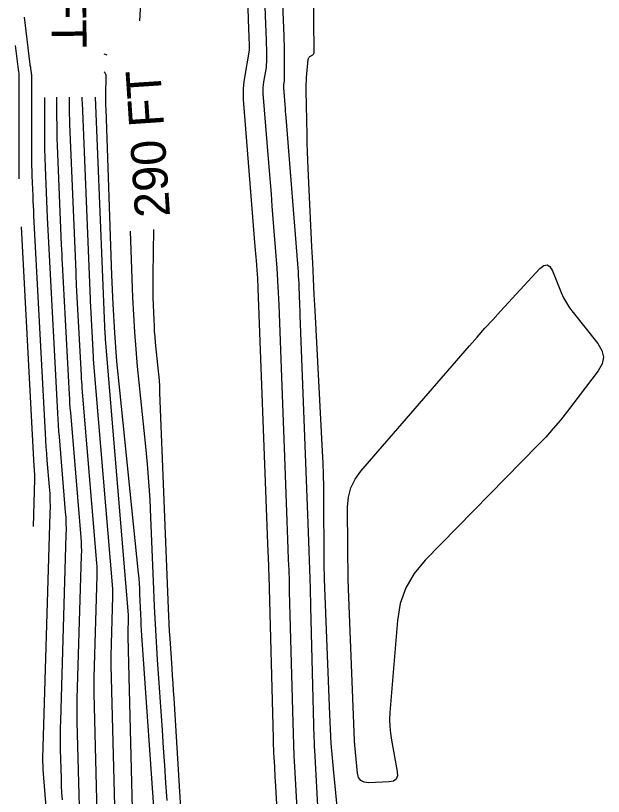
# Model space of a CAD drawing. Extents: x 1768942 to 1774819, y 723037 to 732099.
# Drawn here: x 1770904.7 to 1771006, y 723261.7 to 723396.1 of the extents above; entities that cross this region are included whole.
import ezdxf

# ---------------------------------------------------------------- set-up
doc = ezdxf.new("R2010")
doc.units = 0
doc.layers.add('R_Contour Annot', color=7, linetype='Continuous')
doc.layers.add('R_Contours', color=7, linetype='Continuous')

msp = doc.modelspace()

# ---------------------------------------------------------------- linework, layer by layer
at = {"layer": 'R_Contours'}
for points in [[(1770942.43, 723439.74), (1770944.77, 723395.9), (1770944.79, 723395.4), (1770944.82, 723394.9), (1770944.84, 723394.39), (1770944.86, 723393.89), (1770944.98, 723391.02), (1770944.98, 723390.95), (1770944.99, 723390.87), (1770944.99, 723390.8), (1770944.99, 723390.72), (1770944.99, 723390.43), (1770944.99, 723390.35), (1770944.98, 723390.28), (1770944.98, 723390.2), (1770944.97, 723390.13), (1770944.11, 723385.12), (1770943.99, 723384.26), (1770943.93, 723383.39), (1770943.92, 723382.53), (1770943.96, 723381.66), (1770945.97, 723356.33), (1770946.02, 723355.73), (1770946.07, 723355.13), (1770946.11, 723354.54), (1770946.16, 723353.94), (1770946.35, 723351.54), (1770946.39, 723350.95), (1770946.43, 723350.35), (1770946.46, 723349.75), (1770946.49, 723349.15), (1770948.03, 723308.3), (1770948.09, 723306.75), (1770948.15, 723305.2), (1770948.29, 723301.43), (1770948.31, 723300.99), (1770948.32, 723300.54), (1770948.34, 723300.09), (1770948.35, 723299.65), (1770949.08, 723271.71), (1770949.1, 723271.1), (1770949.13, 723270.49), (1770949.15, 723269.88), (1770949.18, 723269.26), (1770949.31, 723266.81), (1770949.35, 723266.2), (1770949.38, 723265.59), (1770949.42, 723264.97), (1770949.45, 723264.36), (1770951.02, 723237.64)], [(1770949.41, 723429.56), (1770950.93, 723392.61), (1770950.96, 723391.85), (1770950.98, 723391.09), (1770950.99, 723390.34), (1770951, 723389.58), (1770951.02, 723385.31), (1770951.02, 723385.18), (1770951.01, 723385.04), (1770951, 723384.91), (1770950.98, 723384.78), (1770950.89, 723384.25), (1770950.87, 723384.11), (1770950.86, 723383.98), (1770950.86, 723383.85), (1770950.87, 723383.71), (1770951.1, 723380.71), (1770951.15, 723380.17), (1770951.19, 723379.62), (1770951.23, 723379.08), (1770951.28, 723378.53), (1770953.39, 723351.91), (1770953.43, 723351.29), (1770953.47, 723350.68), (1770953.5, 723350.06), (1770953.53, 723349.44), (1770953.65, 723346.35), (1770953.69, 723345.12), (1770953.72, 723344.5), (1770955.13, 723307.22), (1770955.24, 723303.99), (1770955.35, 723300.76), (1770955.45, 723297.54), (1770955.54, 723294.31), (1770956.13, 723271.77), (1770956.15, 723271.24), (1770956.17, 723270.71), (1770956.19, 723270.19), (1770956.22, 723269.66), (1770958.22, 723232.37)], [(1770953.56, 723253.48), (1770952.84, 723266.77), (1770952.75, 723268.68), (1770952.67, 723270.6), (1770952.59, 723272.52), (1770952.54, 723274.44), (1770951.94, 723296.98), (1770951.89, 723298.82), (1770951.84, 723300.65), (1770951.77, 723302.49), (1770951.71, 723304.33), (1770951.11, 723320.17), (1770951, 723323.21), (1770950.88, 723326.24), (1770950.77, 723329.28), (1770950.65, 723332.31), (1770950.12, 723346.29), (1770950.03, 723348.4), (1770949.92, 723350.51), (1770949.79, 723352.62), (1770949.63, 723354.73), (1770948.95, 723363.3), (1770948.79, 723365.34), (1770948.63, 723367.38), (1770948.47, 723369.42), (1770948.3, 723371.46), (1770947.41, 723382.69), (1770947.39, 723383.19), (1770947.4, 723383.69), (1770947.43, 723384.19), (1770947.5, 723384.68), (1770947.87, 723386.84), (1770947.93, 723387.25), (1770947.97, 723387.66), (1770948, 723388.08), (1770948, 723388.49), (1770947.99, 723390.15), (1770947.99, 723390.57), (1770947.98, 723390.98), (1770947.97, 723391.4), (1770947.95, 723391.82), (1770947.3, 723407.78)], [(1770960.52, 723255.88), (1770959.54, 723265.83), (1770959.31, 723268.32), (1770959.12, 723270.81), (1770958.96, 723273.3), (1770958.85, 723275.8), (1770957.96, 723299.07), (1770957.93, 723299.96), (1770957.91, 723300.85), (1770957.89, 723301.73), (1770957.89, 723302.62), (1770957.84, 723313.02), (1770957.82, 723315.05), (1770957.77, 723317.08), (1770957.7, 723319.11), (1770957.61, 723321.14), (1770956.33, 723345.33), (1770956.18, 723348.07), (1770956.04, 723350.8), (1770955.91, 723353.53), (1770955.78, 723356.27), (1770955.15, 723369.76), (1770955.09, 723371.21), (1770955.04, 723372.67), (1770954.99, 723374.12), (1770954.96, 723375.58), (1770954.79, 723383.16), (1770954.79, 723383.73), (1770954.8, 723384.31), (1770954.83, 723384.88), (1770954.87, 723385.45), (1770955.15, 723388.56), (1770955.17, 723388.7), (1770955.23, 723388.83), (1770955.32, 723388.94), (1770955.43, 723389.03), (1770955.94, 723389.35), (1770956.05, 723389.44), (1770956.13, 723389.55), (1770956.18, 723389.68), (1770956.19, 723389.82), (1770955.98, 723406.45)], [(1770926.32, 723399.26), (1770926.1, 723395.17)], [(1770912.29, 723231.13), (1770909.49, 723266.36), (1770909.48, 723266.52), (1770909.47, 723266.68), (1770909.46, 723266.84), (1770909.46, 723267), (1770909.44, 723267.64), (1770909.44, 723267.8), (1770909.44, 723267.96), (1770909.44, 723268.12), (1770909.44, 723268.28), (1770910.7, 723310.38), (1770910.72, 723311.53), (1770910.71, 723312.68), (1770910.66, 723313.83), (1770910.58, 723314.98), (1770910.19, 723319.58), (1770910.1, 723320.73), (1770910.02, 723321.88), (1770909.94, 723323.03), (1770909.88, 723324.19), (1770907.9, 723361.65), (1770907.86, 723362.51), (1770907.81, 723363.37), (1770907.77, 723364.23), (1770907.74, 723365.09), (1770907.6, 723368.53), (1770907.57, 723369.39), (1770907.54, 723370.25), (1770907.53, 723371.11), (1770907.53, 723371.97), (1770907.54, 723385.56), (1770907.53, 723385.74), (1770907.52, 723385.92), (1770907.5, 723386.09), (1770907.48, 723386.27), (1770907.35, 723386.98), (1770907.33, 723387.16), (1770907.3, 723387.34), (1770907.27, 723387.52), (1770907.25, 723387.7), (1770906.27, 723395.84)], [(1770905.36, 723368.02), (1770905.37, 723385.75), (1770905.37, 723385.84), (1770905.36, 723385.93), (1770905.36, 723386.02), (1770905.34, 723386.11), (1770905.28, 723386.46), (1770905.27, 723386.55), (1770905.25, 723386.64), (1770905.24, 723386.73), (1770905.23, 723386.82), (1770904.73, 723390.92)], [(1770920.48, 723389.27), (1770919.97, 723389.46)], [(1770920, 723386.39), (1770920.02, 723386.38), (1770920.07, 723386.34), (1770920.1, 723386.3), (1770920.13, 723386.25), (1770920.23, 723386.02), (1770920.26, 723385.97), (1770920.27, 723385.91), (1770920.28, 723385.85), (1770920.28, 723385.79), (1770920.23, 723382.36), (1770920.22, 723381.76), (1770920.22, 723381.17), (1770920.23, 723380.58), (1770920.25, 723379.98), (1770921.24, 723351.4), (1770921.46, 723346.44), (1770921.76, 723341.49), (1770922.14, 723336.54), (1770922.61, 723331.6), (1770925.85, 723300.15), (1770925.94, 723299.25), (1770926.01, 723298.36), (1770926.06, 723297.47), (1770926.1, 723296.57), (1770926.24, 723293), (1770926.28, 723292.1), (1770926.33, 723291.21), (1770926.38, 723290.31), (1770926.44, 723289.42), (1770928.78, 723255.77)], [(1770909.7, 723382.02), (1770909.69, 723376.37), (1770909.7, 723374.78), (1770909.73, 723373.2), (1770909.77, 723371.61), (1770909.82, 723370.02), (1770910.18, 723361.35), (1770910.23, 723360.27), (1770910.28, 723359.19), (1770910.33, 723358.11), (1770910.38, 723357.03), (1770911.94, 723327.65), (1770911.99, 723326.63), (1770912.06, 723325.61), (1770912.13, 723324.59), (1770912.21, 723323.57), (1770913.29, 723310.7), (1770913.36, 723309.7), (1770913.4, 723308.7), (1770913.42, 723307.71), (1770913.4, 723306.71), (1770912.44, 723274.72), (1770912.41, 723273.48), (1770912.4, 723272.25), (1770912.41, 723271.01), (1770912.43, 723269.77), (1770912.56, 723264.82), (1770912.6, 723263.58), (1770912.66, 723262.34), (1770912.73, 723261.11)], [(1770915.75, 723260), (1770915.68, 723261.99), (1770915.36, 723274.53), (1770915.34, 723275.53), (1770915.33, 723276.53), (1770915.34, 723277.53), (1770915.36, 723278.53), (1770916.1, 723303.18), (1770916.12, 723303.96), (1770916.11, 723304.73), (1770916.07, 723305.5), (1770916.02, 723306.27), (1770914.22, 723327.78), (1770914.15, 723328.56), (1770914.1, 723329.34), (1770914.05, 723330.12), (1770914, 723330.9), (1770912.82, 723353.36), (1770912.78, 723354.19), (1770912.74, 723355.01), (1770912.7, 723355.84), (1770912.66, 723356.66), (1770911.96, 723373.71), (1770911.92, 723374.93), (1770911.88, 723376.14), (1770911.87, 723377.36), (1770911.86, 723378.58), (1770911.86, 723382.03)], [(1770918.87, 723256.61), (1770918.28, 723279.4), (1770918.26, 723280.11), (1770918.26, 723280.82), (1770918.27, 723281.52), (1770918.28, 723282.23), (1770918.81, 723299.66), (1770918.81, 723300.21), (1770918.81, 723300.75), (1770918.79, 723301.3), (1770918.75, 723301.84), (1770916.22, 723331.99), (1770916.18, 723332.53), (1770916.14, 723333.07), (1770916.1, 723333.61), (1770916.07, 723334.15), (1770915.25, 723349.69), (1770915.22, 723350.26), (1770915.19, 723350.83), (1770915.17, 723351.4), (1770915.14, 723351.97), (1770914.1, 723377.39), (1770914.07, 723378.24), (1770914.04, 723379.09), (1770914.03, 723379.94), (1770914.03, 723380.79), (1770914.03, 723382.05)], [(1770922.05, 723251.22), (1770921.2, 723284.28), (1770921.19, 723284.69), (1770921.19, 723285.1), (1770921.19, 723285.52), (1770921.2, 723285.93), (1770921.51, 723296.13), (1770921.51, 723296.45), (1770921.51, 723296.77), (1770921.5, 723297.09), (1770921.47, 723297.41), (1770918.22, 723336.19), (1770918.2, 723336.49), (1770918.18, 723336.79), (1770918.16, 723337.09), (1770918.14, 723337.39), (1770917.69, 723346.02), (1770917.67, 723346.34), (1770917.65, 723346.65), (1770917.64, 723346.97), (1770917.63, 723347.29), (1770916.23, 723381.08), (1770916.22, 723381.56), (1770916.2, 723382.04), (1770916.2, 723382.07)], [(1770925.24, 723245.83), (1770924.12, 723289.15), (1770924.12, 723289.27), (1770924.12, 723289.39), (1770924.12, 723289.51), (1770924.12, 723289.63), (1770924.21, 723292.61), (1770924.21, 723292.7), (1770924.21, 723292.8), (1770924.21, 723292.89), (1770924.2, 723292.98), (1770920.23, 723340.4), (1770920.22, 723340.46), (1770920.22, 723340.52), (1770920.21, 723340.58), (1770920.21, 723340.64), (1770920.12, 723342.35), (1770920.12, 723342.41), (1770920.11, 723342.48), (1770920.11, 723342.54), (1770920.11, 723342.6), (1770918.48, 723382.08)], [(1770907.83, 723308.15), (1770908.07, 723316.29), (1770908.07, 723316.47), (1770908.07, 723316.66), (1770908.06, 723316.85), (1770908.05, 723317.03), (1770907.99, 723317.78), (1770907.97, 723317.97), (1770907.96, 723318.15), (1770907.95, 723318.34), (1770907.94, 723318.53), (1770905.76, 723359.75)], [(1770924.49, 723358.98), (1770924.89, 723347.55), (1770925.02, 723344.58), (1770925.19, 723341.62), (1770925.42, 723338.66), (1770925.7, 723335.71), (1770927.12, 723321.94), (1770927.41, 723318.89), (1770927.65, 723315.84), (1770927.85, 723312.78), (1770927.99, 723309.71), (1770928.47, 723297.4), (1770928.6, 723294.37), (1770928.75, 723291.33), (1770928.93, 723288.29), (1770929.13, 723285.26), (1770929.97, 723273.12), (1770930.18, 723270.09), (1770930.38, 723267.05), (1770930.58, 723264.02), (1770930.77, 723260.98)], [(1770928.49, 723359.25), (1770928.36, 723351.46), (1770928.35, 723350.49), (1770928.36, 723349.52), (1770928.37, 723348.55), (1770928.4, 723347.58), (1770928.53, 723343.7), (1770928.58, 723342.73), (1770928.63, 723341.76), (1770928.71, 723340.79), (1770928.8, 723339.82), (1770929.25, 723335.43), (1770929.35, 723334.37), (1770929.44, 723333.32), (1770929.5, 723332.26), (1770929.55, 723331.2), (1770931, 723294.02), (1770931.05, 723292.73), (1770931.12, 723291.45), (1770931.19, 723290.17), (1770931.28, 723288.88), (1770931.63, 723283.75), (1770931.72, 723282.47), (1770931.81, 723281.19), (1770931.89, 723279.9), (1770931.97, 723278.62), (1770934.13, 723243.64)]]:
    msp.add_lwpolyline(points, dxfattribs=at)
msp.add_lwpolyline([(1770962.05, 723299.22), (1770962.01, 723300.98), (1770961.98, 723302.73), (1770961.96, 723304.49), (1770961.93, 723311.52), (1770962.07, 723313.22), (1770962.5, 723314.82), (1770963.21, 723316.31), (1770964.22, 723317.69), (1770982.93, 723339.27), (1770984.25, 723340.77), (1770985.58, 723342.27), (1770986.92, 723343.75), (1770988.27, 723345.23), (1770995.06, 723352.55), (1770995.71, 723353.09), (1770996.28, 723353.2), (1770996.78, 723352.89), (1770997.2, 723352.17), (1770998.73, 723348.43), (1770999.14, 723347.52), (1770999.62, 723346.64), (1771000.16, 723345.79), (1771000.76, 723344.99), (1771005.05, 723339.63), (1771005.75, 723338.47), (1771005.99, 723337.3), (1771005.78, 723336.13), (1771005.11, 723334.96), (1770999.81, 723328.02), (1770998.61, 723326.49), (1770997.36, 723325), (1770996.06, 723323.55), (1770994.71, 723322.14), (1770975.27, 723302.38), (1770973.37, 723300.1), (1770971.95, 723297.6), (1770970.99, 723294.89), (1770970.51, 723291.96), (1770969.22, 723276.16), (1770969.16, 723274.96), (1770969.18, 723273.76), (1770969.29, 723272.57), (1770969.47, 723271.39), (1770970.49, 723266.01), (1770970.52, 723265.25), (1770970.3, 723264.7), (1770969.81, 723264.35), (1770969.07, 723264.21), (1770965.56, 723264.06), (1770964.79, 723264.14), (1770964.21, 723264.44), (1770963.83, 723264.97), (1770963.64, 723265.73), (1770963.16, 723270.54), (1770963.15, 723270.74), (1770963.13, 723270.93), (1770963.12, 723271.13), (1770963.11, 723271.33), (1770962.11, 723297.46)], close=True, dxfattribs=at)

# ---------------------------------------------------------------- texts
at = {"layer": 'R_Contour Annot'}
for rotation, p in [(270.4204, (1770910.78, 723415.92)), (93.8217, (1770931.35, 723361.55))]:
    msp.add_text('290 FT', height=6, rotation=rotation, dxfattribs=at).set_placement(p)

doc.saveas('drawing.dxf')
